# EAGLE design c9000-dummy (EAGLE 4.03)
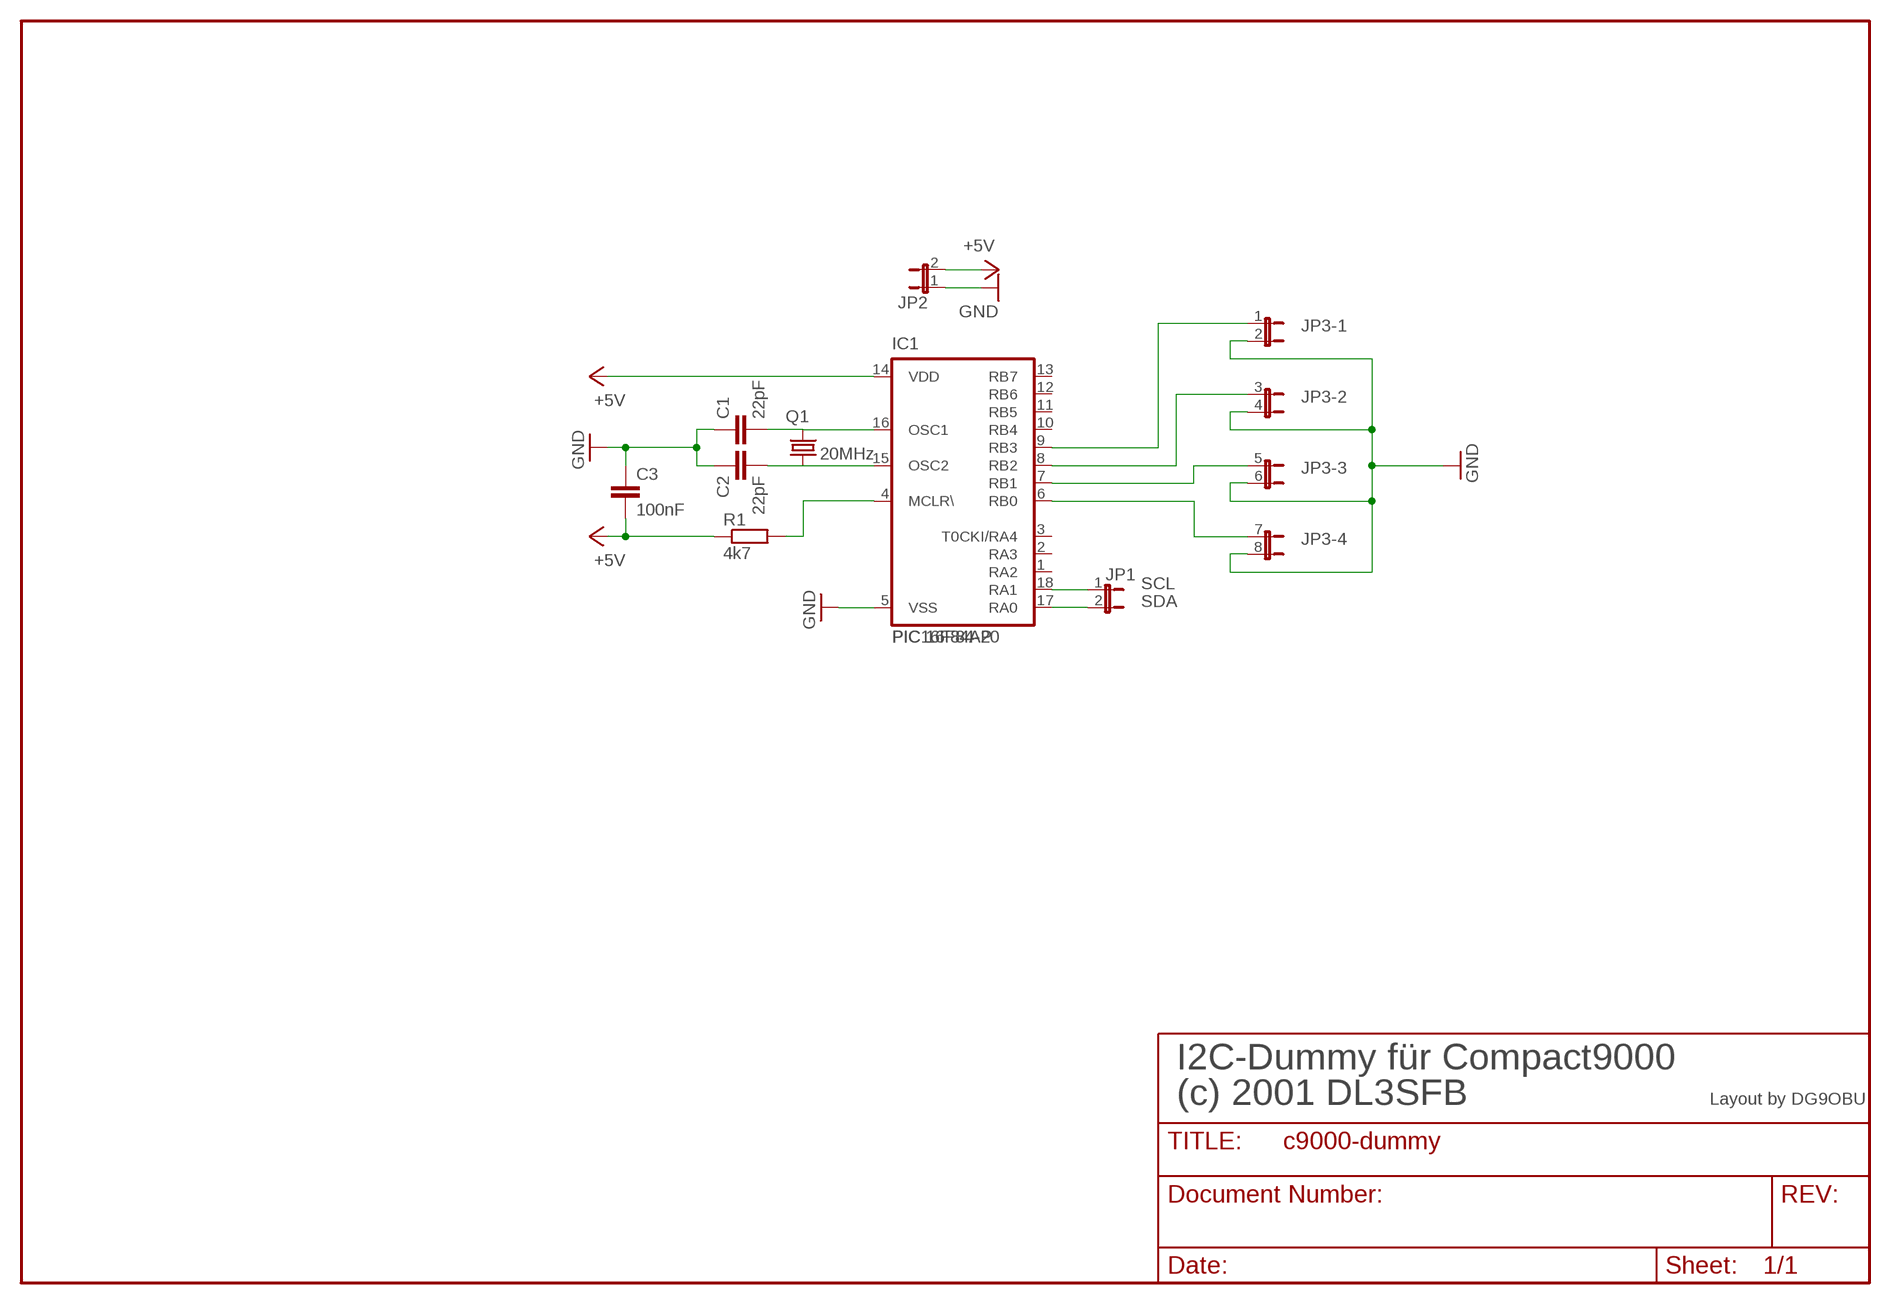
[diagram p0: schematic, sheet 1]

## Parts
C1  22pF  C-EU025-024X044  [C025-024X044]
C2  22pF  C-EU025-024X044  [C025-024X044]
C3  100nF  C-EU025-050X050  [C025-050X050]
IC1  PIC16F84AP  [DIL18]
JP1  JP1E  [JP1]
JP2  JP1E  [JP1]
JP3  JP4QE  [JP4Q]
Q1  20MHz  HC49/S  [HC49/S]
R1  4k7  R-EU_0204/7  [0204/7]

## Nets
+5V: C3.1 IC1.14(VDD) JP2.2 R1.1
GND: C1.2 C2.1 C3.2 IC1.5(VSS) JP2.1 JP3.2 JP3.4 JP3.6 JP3.8
N$1: IC1.18(RA1) JP1.1
N$2: IC1.17(RA0) JP1.2
N$3: IC1.6(RB0) JP3.7
N$4: IC1.7(RB1) JP3.5
N$5: IC1.8(RB2) JP3.3
N$6: IC1.9(RB3) JP3.1
N$11: C1.1 IC1.16(OSC1) Q1.2
N$12: C2.2 IC1.15(OSC2) Q1.1
N$15: IC1.4(MCLR\) R1.2
Unconnected: IC1.1(RA2) IC1.2(RA3) IC1.3(T0CKI/RA4) IC1.10(RB4) IC1.11(RB5) IC1.12(RB6) IC1.13(RB7)

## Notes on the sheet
- SCL
- SDA
- PIC 16F84-20
- I2C-Dummy für Compact9000
- (c) 2001 DL3SFB | Layout by DG9OBU

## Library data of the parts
C1-C3 = rcl:C-EU: CAPACITOR, European symbol
IC1 = microchip:PIC16F8*: MICROCONTROLLER 8-Bit PIC16F8X Family - CMOS Flash/EEPROM Pin Compatible : PIC16F83, PIC16CR83, PIC16F84A, PIC16CR84 see also PIC16C*
JP1 JP2 = jumper:JP1E: JUMPER
JP3 = jumper:JP4QE: JUMPER
Q1 = crystal:HC49/S: CRYSTAL
R1 = rcl:R-EU_: RESISTOR, European symbol

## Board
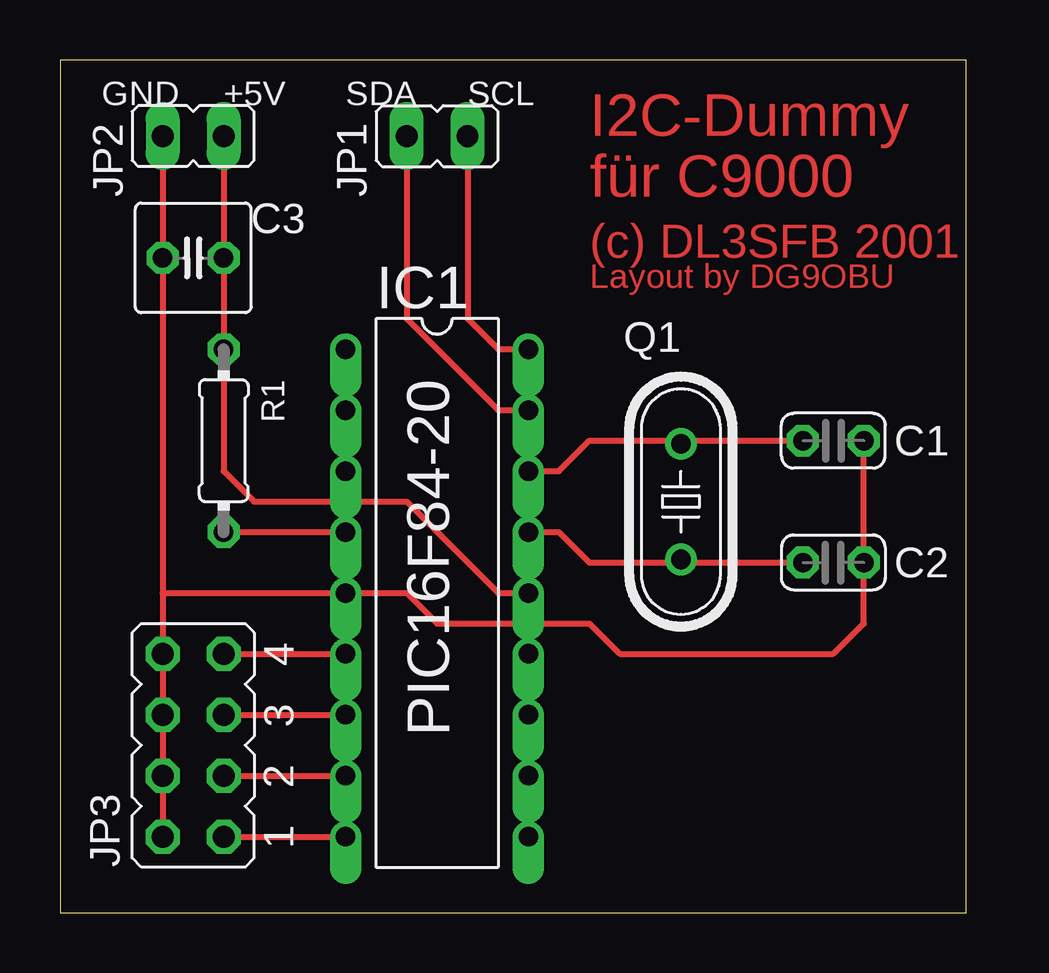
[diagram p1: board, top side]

Size 37.77 x 35.55 mm. Coordinates in mm from the lower left corner, seen from the top.
Outline: 0,0 37.77,0 37.77,35.55 0,35.55 0,0
Copper layers used: Top

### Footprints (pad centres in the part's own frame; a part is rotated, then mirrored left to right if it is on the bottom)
C025-024X044 = drill 0.813 octagon: 1 -1.27,0; 2 1.27,0
C025-050X050 = drill 0.813 octagon: 1 -1.27,0; 2 1.27,0
DIL18 = drill 0.813 offset: 1 -10.16,-3.81; 2 -7.62,-3.81; 3 -5.08,-3.81; 4 -2.54,-3.81; 5 0,-3.81; 6 2.54,-3.81; 7 5.08,-3.81; 8 7.62,-3.81; 9 10.16,-3.81; 10 10.16,3.81; 11 7.62,3.81; 12 5.08,3.81; 13 2.54,3.81; 14 0,3.81; 15 -2.54,3.81; 16 -5.08,3.81; 17 -7.62,3.81; 18 -10.16,3.81
JP1 = drill 0.914 long: 1 0,-1.27; 2 0,1.27
JP4Q = drill 0.914 octagon: 1 -3.81,-1.27; 2 -3.81,1.27; 3 -1.27,-1.27; 4 -1.27,1.27; 5 1.27,-1.27; 6 1.27,1.27; 7 3.81,-1.27; 8 3.81,1.27
HC49/S = drill 0.813 round: 1 -2.413,0; 2 2.413,0
0204/7 = drill 0.813 octagon: 1 -3.81,0; 2 3.81,0

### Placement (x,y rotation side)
C1  32.22,19.68 0 top
C2  32.22,14.6 180 top
C3  5.55,27.3 180 top
IC1  15.71,13.33 270 top
JP1  15.71,32.38 90 top
JP2  5.55,32.38 270 top
JP3  5.55,6.98 90 top
Q1  25.87,17.14 90 top
R1  6.82,19.68 270 top

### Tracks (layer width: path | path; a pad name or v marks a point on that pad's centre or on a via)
+5V
  Top 0.254: JP2.2 C3.1 R1.1 6.82,18.41 8.09,17.14 14.44,17.14 18.25,13.33 IC1.14
GND
  Top 0.254: JP2.1 C3.2 4.28,13.33 | C1.2 C2.1 33.49,12.06 32.22,10.79 23.33,10.79 22.06,12.06 15.71,12.06 14.44,13.33 IC1.5 4.28,13.33 | 4.28,13.33 JP3.8 JP3.6 JP3.4 JP3.2
N$1
  Top 0.254: IC1.18 18.25,23.49 16.98,24.76 JP1.1
N$2
  Top 0.254: IC1.17 18.25,20.95 14.44,24.76 JP1.2
N$3
  Top 0.254: JP3.7 IC1.6
N$4
  Top 0.254: JP3.5 IC1.7
N$5
  Top 0.254: JP3.3 IC1.8
N$6
  Top 0.254: JP3.1 IC1.9
N$11
  Top 0.254: 25.87,19.68 C1.1 | 25.87,19.68 22.06,19.68 20.79,18.41 IC1.16 | 25.87,19.68 Q1.2
N$12
  Top 0.254: 25.87,14.6 22.06,14.6 20.79,15.87 IC1.15 | 25.87,14.6 C2.2 | 25.87,14.6 Q1.1
N$15
  Top 0.254: R1.2 IC1.4

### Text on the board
Top: I2C-Dummy | für C9000 | (c) DL3SFB 2001 | Layout by DG9OBU
tNames: GND | +5V | SDA | SCL | PIC16F84-20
